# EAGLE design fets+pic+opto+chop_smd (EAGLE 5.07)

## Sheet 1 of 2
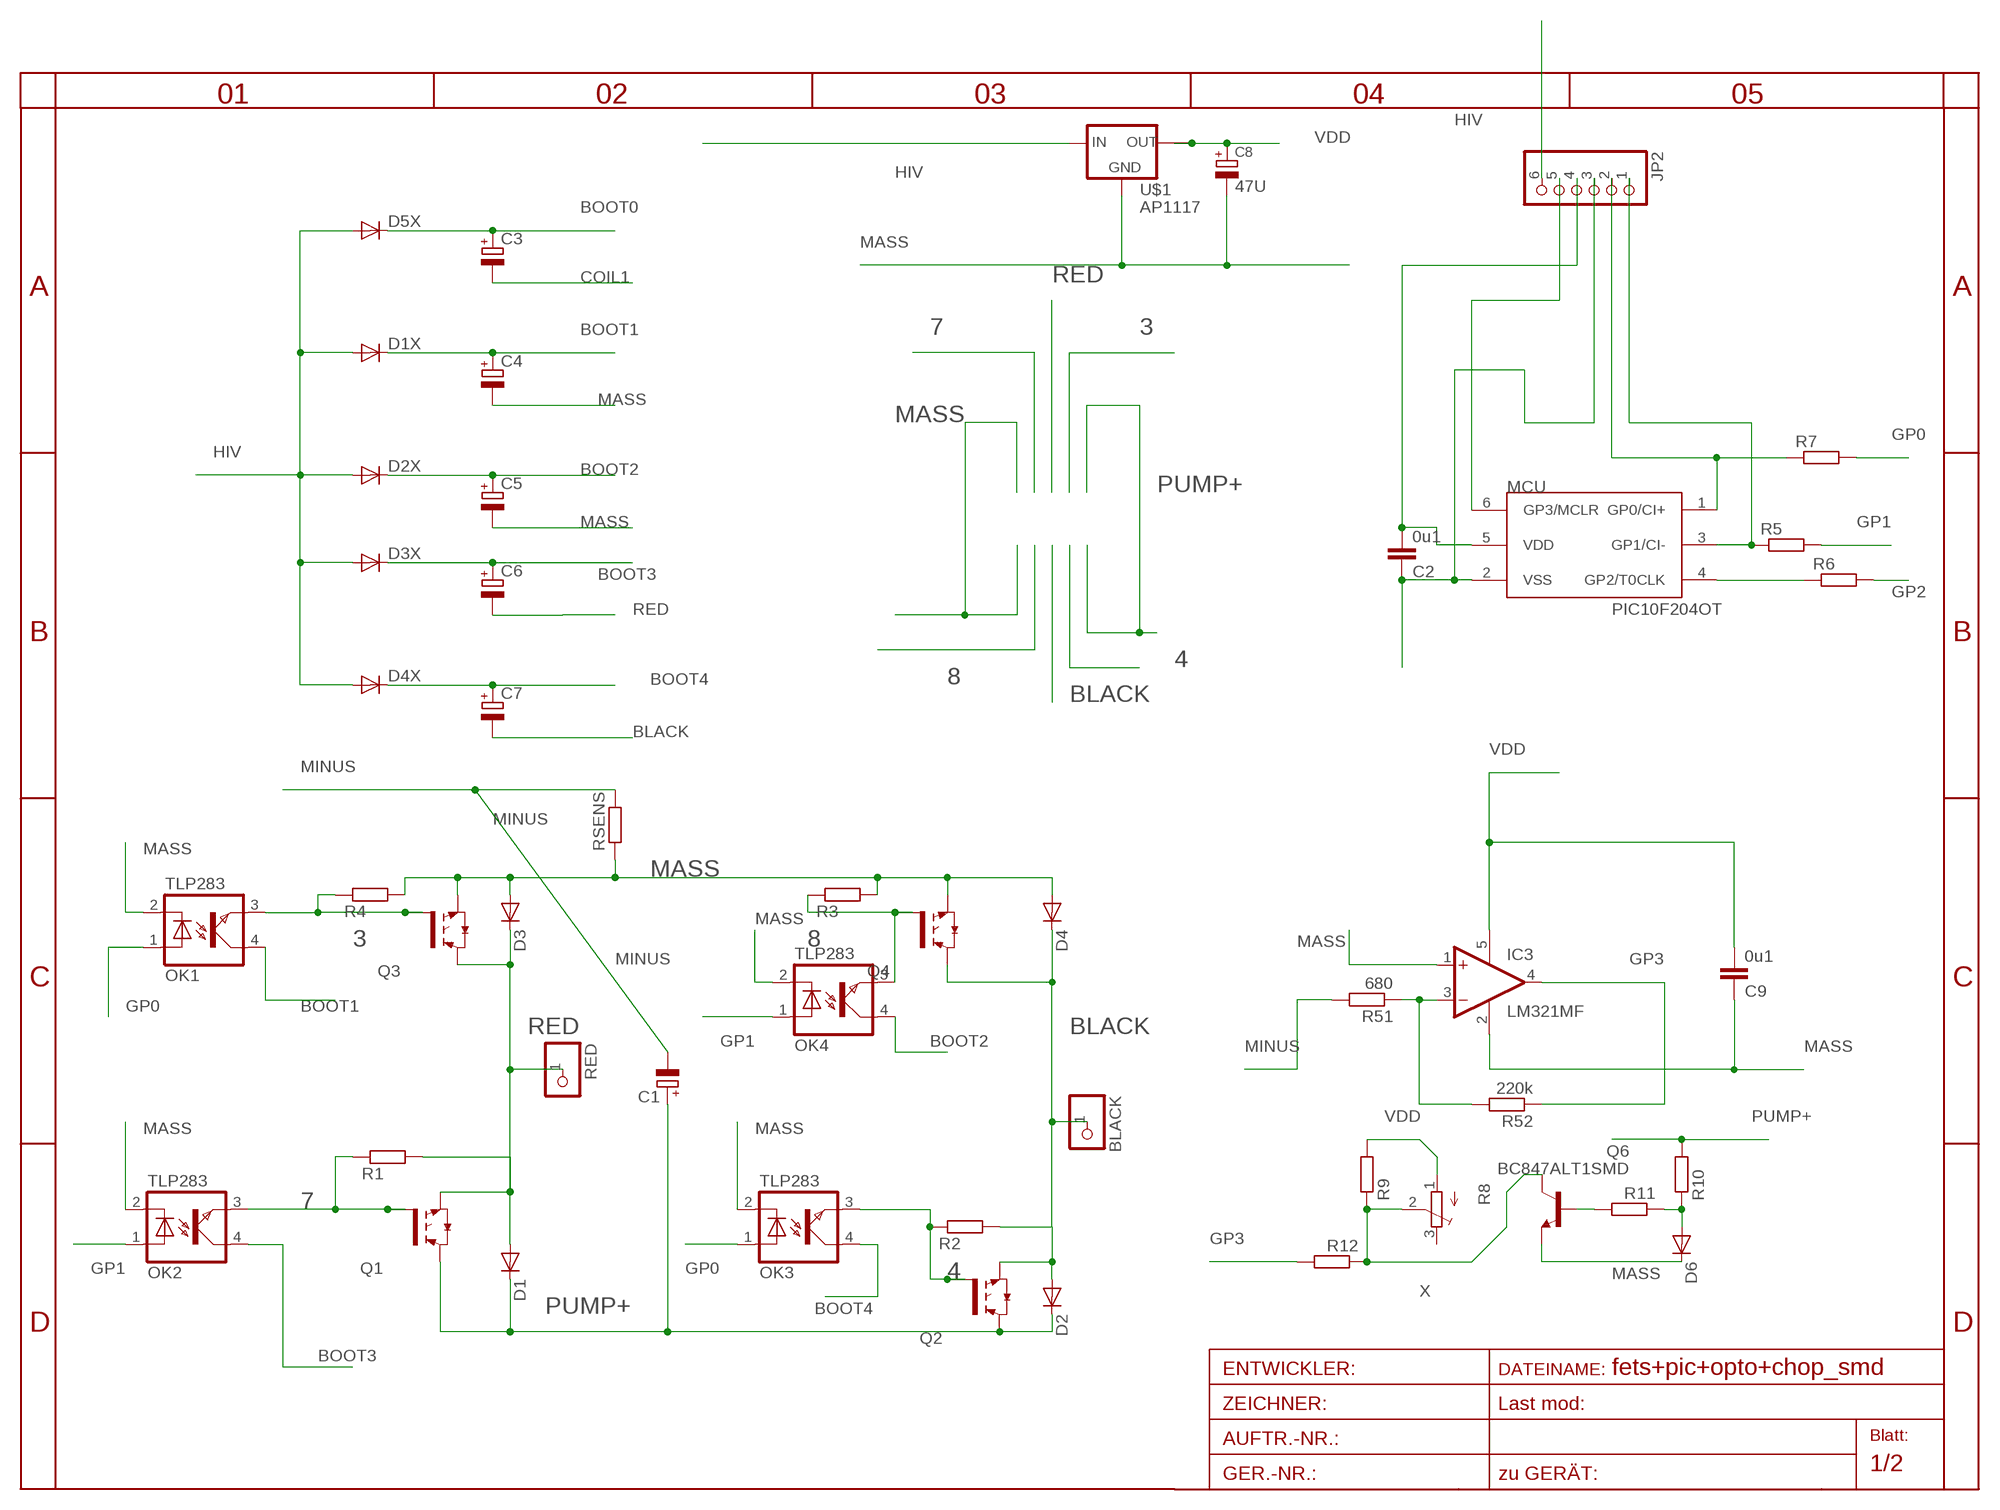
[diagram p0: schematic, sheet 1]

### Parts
BLACK  PINHD-1X14.5MM  [1X4MM5]
C1  CPOL-EUE5-13  [E5-13]
C2  0u1  C-EUC1206  [C1206]
C3  CPOL-EUC  [PANASONIC_C]
C4  CPOL-EUC  [PANASONIC_C]
C5  CPOL-EUC  [PANASONIC_C]
C6  CPOL-EUC  [PANASONIC_C]
C7  CPOL-EUC  [PANASONIC_C]
C8  47U  CPOL-EUC  [PANASONIC_C]
C9  0u1  C-EUC1206  [C1206]
D1  DIODE-SMC  [SMC]
D1X  DIODE-SMA-DO214  [SMA-DO214AC]
D2  DIODE-SMC  [SMC]
D2X  DIODE-SMA-DO214  [SMA-DO214AC]
D3  DIODE-SMC  [SMC]
D3X  DIODE-SMA-DO214  [SMA-DO214AC]
D4  DIODE-SMC  [SMC]
D4X  DIODE-SMA-DO214  [SMA-DO214AC]
D5X  DIODE-SMA-DO214  [SMA-DO214AC]
D6  DIODE-MINIMELF  [MINIMELF]
IC3  LM321MF  [SOT23-5]
JP2  PINHD-1X6  [1X06BOX]
MCU  PIC10F204OT  [SOT23-6]
OK1  TLP283  [MINI-FLAT-4]
OK2  TLP283  [MINI-FLAT-4]
OK3  TLP283  [MINI-FLAT-4]
OK4  TLP283  [MINI-FLAT-4]
Q1  IRG4BC15UD-S  [D2PACK]
Q2  IRG4BC15UD-S  [D2PACK]
Q3  IRG4BC15UD-S  [D2PACK]
Q4  IRG4BC15UD-S  [D2PACK]
Q6  BC847ALT1SMD  [SOT23]
R1  R-EU_R1206  [R1206]
R2  R-EU_R1206  [R1206]
R3  R-EU_R1206  [R1206]
R4  R-EU_R1206  [R1206]
R5  R-EU_R1206  [R1206]
R6  R-EU_R1206  [R1206]
R7  R-EU_R1206  [R1206]
R8  TRIM_EU-3223W  [3223W]
R9  R-EU_R1206  [R1206]
R10  R-EU_R1206  [R1206]
R11  R-EU_R1206  [R1206]
R12  R-EU_R1206  [R1206]
R51  680  R-EU_R0805  [R0805]
R52  220k  R-EU_R0805  [R0805]
RED  PINHD-1X14.5MM  [1X4MM5]
RSENS  R-EU_CERAM50  [CERAM50]
U$1  AP1117  [SOT223]

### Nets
3: OK1.3(EMIT) Q3.1(G) R4.1
4: OK3.3(EMIT) Q2.1(G) R2.1
7: OK2.3(EMIT) Q1.1(G) R1.1
8: OK4.3(EMIT) Q4.1(G) R3.1
BLACK: BLACK.1 C7.- D2.A D4.C Q2.3(E) Q4.2(C) R2.2
BOOT0: C3.+ D5X.K(C) ; also sheet 2
BOOT1: C4.+ D1X.K(C) OK1.4(COL)
BOOT2: C5.+ D2X.K(C) OK4.4(COL)
BOOT3: C6.+ D3X.K(C) OK2.4(COL)
BOOT4: C7.+ D4X.K(C) OK3.4(COL)
COIL1: C3.- ; also sheet 2
GP0: OK1.1(A) OK3.1(A) R7.2
GP0I: JP2.2 MCU.1(GP0/CI+) R7.1
GP1: OK2.1(A) OK4.1(A) R5.2
GP1I: JP2.1 MCU.3(GP1/CI-) R5.1
GP2: R6.2 ; also sheet 2
GP2I: MCU.4(GP2/T0CLK) R6.1
GP3: IC3.4(OUT) JP2.5 MCU.6(GP3/MCLR) R12.2 R52.1
HIV: D1X.A D2X.A D3X.A D4X.A D5X.A JP2.6 U$1.3(IN) ; also sheet 2
MASS: C2.1 C4.- C5.- C8.- C9.1 D3.A D4.A D6.C IC3.1(+IN) IC3.2(V-) JP2.3 MCU.2(VSS) OK1.2(C) OK2.2(C) OK3.2(C) OK4.2(C) Q3.3(E) Q4.3(E) Q6.2(E) R3.2 R4.2 RSENS.1 U$1.1(GND) ; also sheet 2
MINUS: C1.- R51.2 RSENS.2 ; also sheet 2
N$4: D6.A R10.1 R11.1
N$5: Q6.1(B) R11.2
N$52: IC3.3(-IN) R51.1 R52.2
PUMP+: C1.+ D1.C D2.C Q1.2(C) Q2.2(C) R10.2 ; also sheet 2
RED: C6.- D1.A D3.C Q1.3(E) Q3.2(C) R1.2 RED.1
VDD: C2.2 C8.+ C9.2 IC3.5(V+) JP2.4 MCU.5(VDD) R8.1(A) R9.2 U$1.2(OUT) U$1.4(TAB)
X: Q6.3(C) R8.2(S) R9.1 R12.1
Unconnected: R8.3(E)

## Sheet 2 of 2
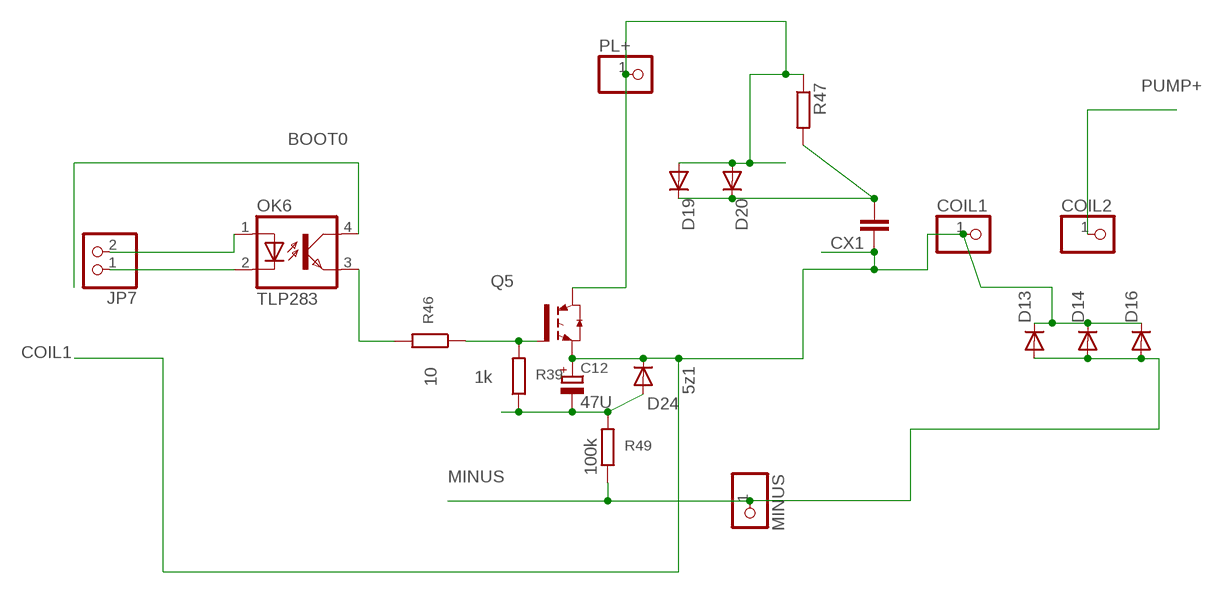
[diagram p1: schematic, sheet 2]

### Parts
C12  47U  CPOL-EUC  [PANASONIC_C]
COIL1  PINHD-1X14.5MM  [1X4MM5]
COIL2  PINHD-1X14.5MM  [1X4MM5]
CX1  CXXC15B6  [XC15B6]
D13  DIODE-SMC  [SMC]
D14  DIODE-SMC  [SMC]
D16  DIODE-SMC  [SMC]
D19  DIODE-SMC  [SMC]
D20  DIODE-SMC  [SMC]
D24  5z1  DIODE-MINIMELF  [MINIMELF]
JP7  PINHD-1X2STR  [1X02]
MINUS  PINHD-1X14.5MM  [1X4MM5]
OK6  TLP283  [MINI-FLAT-4]
PL+  PINHD-1X14.5MM  [1X4MM5]
Q5  IRG4BC15UD-S  [D2PACK]
R39  1k  R-EU_R1206  [R1206]
R46  10  R-EU_R1206  [R1206]
R47  R-EU_0613/15  [P0613/15]
R49  100k  R-EU_R0805  [R0805]

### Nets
BATT-: C12.- D24.A R39.1 R49.2
BOOT0: OK6.4(COL) ; also sheet 1
COIL1: C12.+ COIL1.1 CX1.1 D13.C D14.C D16.C D24.C Q5.3(E) ; also sheet 1
GP2: JP7.2 OK6.1(A) ; also sheet 1
HIV: D19.A D20.A PL+.1 Q5.2(C) R47.1 ; also sheet 1
MASS: JP7.1 OK6.2(C) ; also sheet 1
MINUS: D13.A D14.A D16.A MINUS.1 R49.1 ; also sheet 1
N$43: OK6.3(EMIT) R46.2
N$45: Q5.1(G) R39.2 R46.1
PUMP+: COIL2.1 ; also sheet 1
SNUB: CX1.2 D19.C D20.C R47.2

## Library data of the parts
BLACK COIL1 COIL2 MINUS PL+ RED = pinhead:PINHD-1X1: PIN HEADER
C1 C3-C7 = rcl:CPOL-EU: POLARIZED CAPACITOR, European symbol
C2 C9 = rcl:C-EU: CAPACITOR, European symbol
C8 C12 = rcl-2:CPOL-EU: POLARIZED CAPACITOR, European symbol
CX1 = rcl:CX: X CAPACITOR
D1 D1X D2 D2X D3 D3X D4 D4X D5X D6 D13 D14 D16 D19 D20 D24 = diode:DIODE-: DIODE
IC3 = linear:LM321?*: Low Power Single Op Amp Source: http://cache.national.com/ds/LM/LM321.pdf
JP2 = pinhead:PINHD-1X6: PIN HEADER
JP7 = pinhead:PINHD-1X2: PIN HEADER
MCU = microchip-3:PIC10F2*: uPC nW 0,25/0,5k Program Flash memory Comparator
OK1-OK4 OK6 = optocoupler:TLP283: TOSHIBA PHOTOCOUPLER GaAs IRED & PHOTO-TRANSISTOR Source: http://www.semicon.toshiba.co.jp/td/en/Opto/Photocoupler/en_20050928_TLP283_datasheet.pdf
Q1-Q5 = transistor-power:IRG4BC15UD-: INSULATED GATE BIPOLAR TRANSISTOR WITH ULTRAFAST SOFT RECOVERY DIODE
Q6 = transistor-npn:BC847*: NPN Transistor
R1-R7 R9-R12 R47 R51 R52 RSENS = rcl:R-EU_: RESISTOR, European symbol
R8 = pot:TRIM_EU-: POTENTIOMETER
R39 R46 R49 = rcl-2:R-EU_: RESISTOR, European symbol
U$1 = v-reg:AP1117

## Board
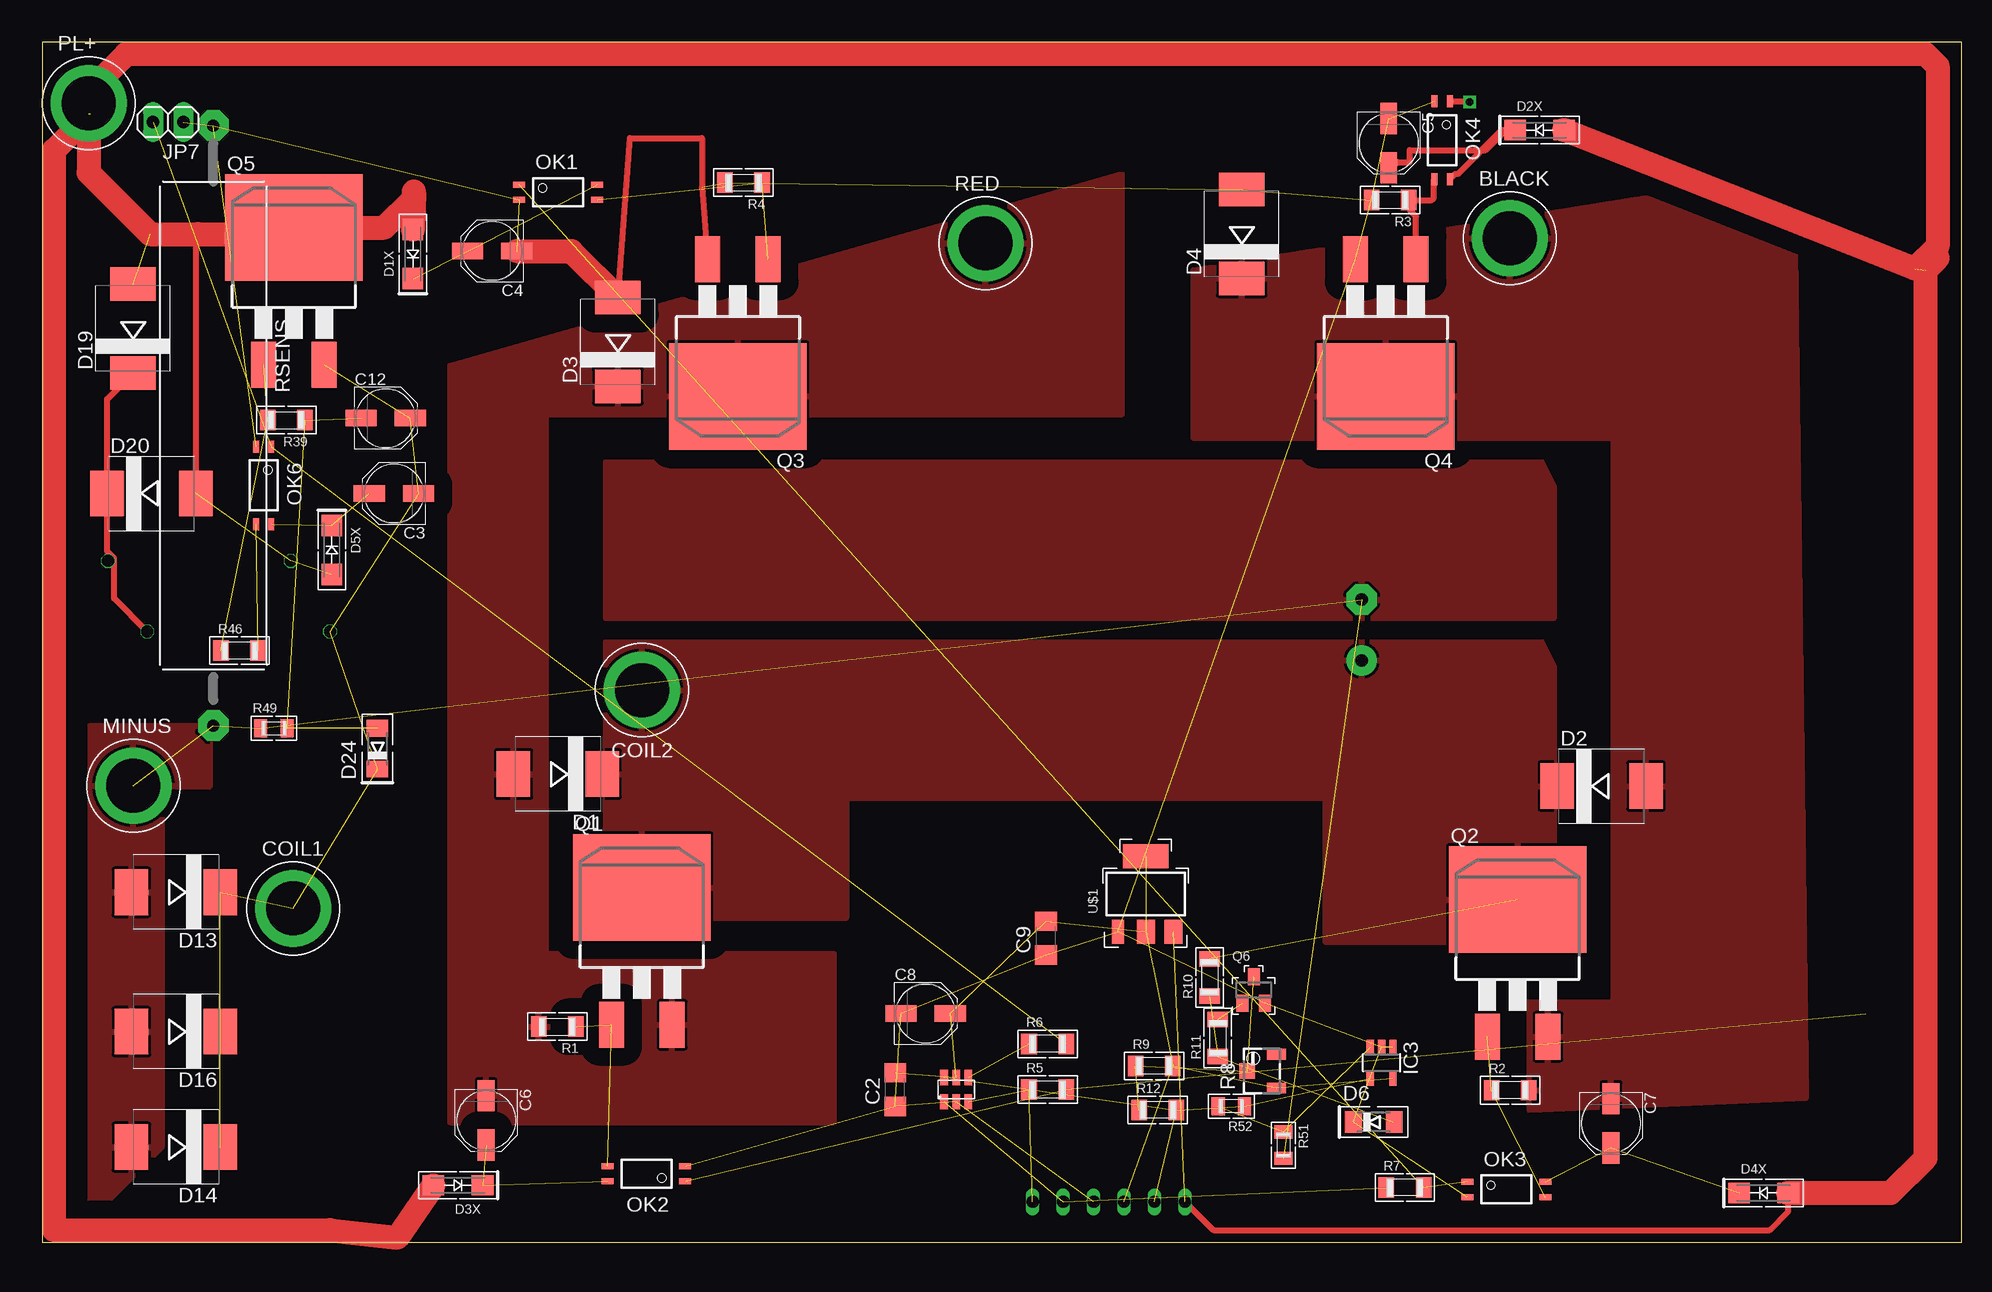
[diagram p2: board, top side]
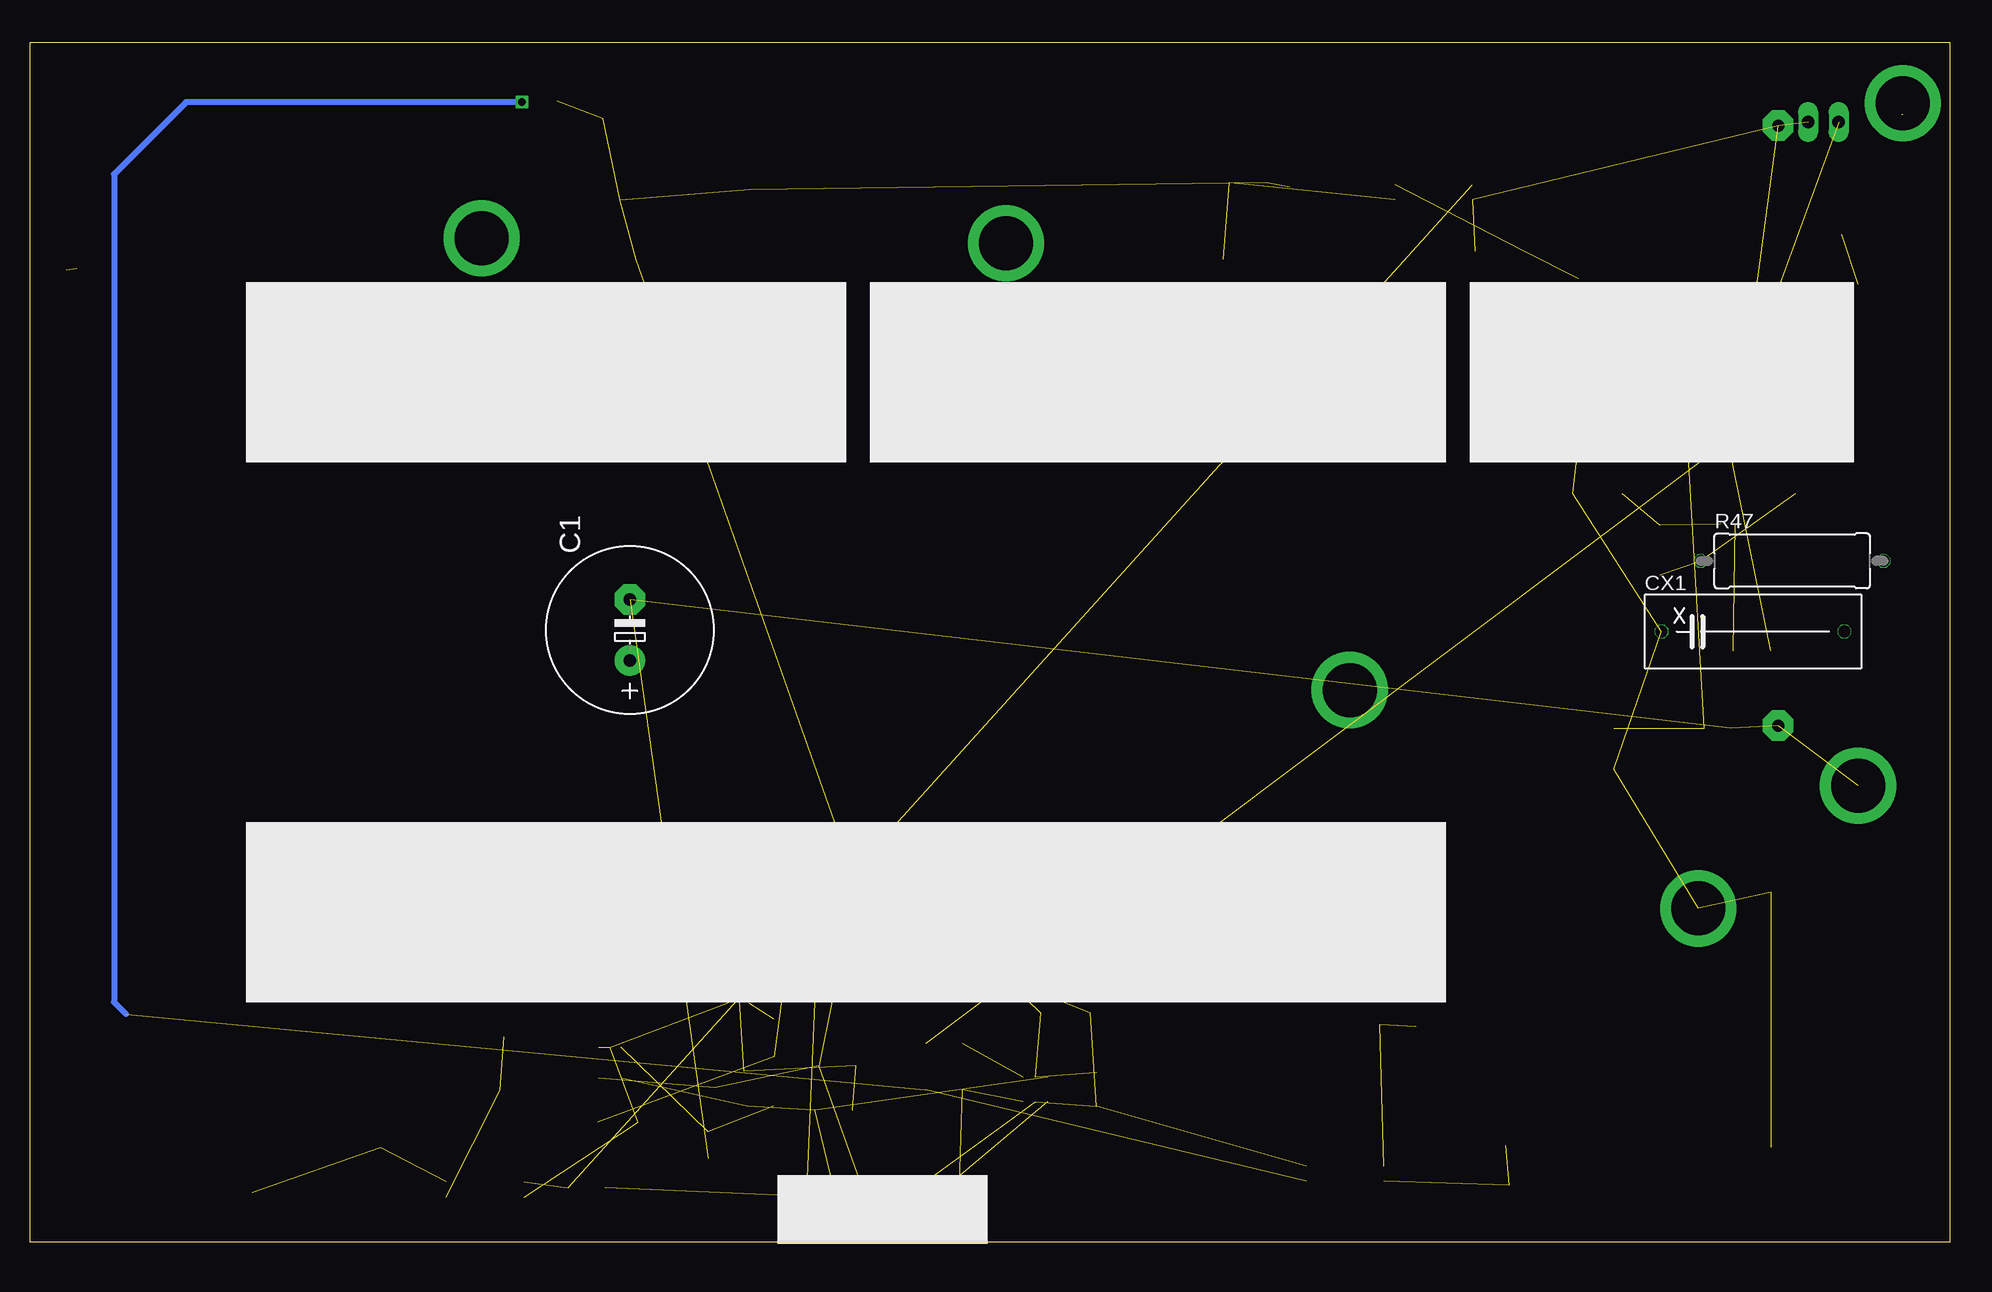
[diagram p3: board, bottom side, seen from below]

Size 160 x 100 mm. Coordinates in mm from the lower left corner, seen from the top.
Outline: 0,0 160,0 160,100 0,100 0,0
Copper layers (1*16): Top 0.035mm / dielectric 1.5mm / Bottom 0.035mm
Design rules "default": minimum track width 10mil, minimum drill 20mil, track to track 8mil, track to pad 8mil, pad to pad 8mil, via to via 8mil, smd to smd 8mil, copper to edge 40mil, drill to drill 8mil, minimum pad ring 1mil, minimum via ring 8mil, stop-mask expansion 4mil, vias tented up to drill 0mil, thermal gap 10mil

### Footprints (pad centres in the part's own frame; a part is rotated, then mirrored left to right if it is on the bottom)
1X4MM5 = drill 4.5 pad 6.35 round: 1 0,0
E5-13 = drill 1.016 pad 2.54 round: + -2.54,0 | drill 1.016 pad 2.54 octagon: - 2.54,0
C1206 = smd 1.6 x 1.8: 1 -1.4,0; 2 1.4,0
PANASONIC_C = smd 2.6 x 1.4: + 2.05,0; - -2.05,0
XC15B6 = drill 1.016 octagon: 1 -7.62,0; 2 7.62,0
SMC = smd 2.8 x 3.8: A 3.7,0; C -3.7,0
SMA-DO214AC = smd 1.8 x 1.7: A 2.05,-0.127; K -2.05,-0.127
MINIMELF = smd 1.4 x 1.8: A 1.7,0; C -1.7,0
SOT23-5 = smd 0.6 x 1.2: 1 -0.95,-1.306; 2 0,-1.306; 3 0.95,-1.306; 4 0.95,1.306; 5 -0.95,1.306
1X06BOX = drill 1.016 long: 1 -6.35,0; 2 -3.81,0; 3 -1.27,0; 4 1.27,0; 5 3.81,0; 6 6.35,0
1X02 = drill 1.016 pad 1.676 long: 1 -1.27,0; 2 1.27,0
SOT23-6 = smd 0.635 x 1.27: 1 -1.016,-1.016; 2 0,-1.016; 3 1.016,-1.016; 4 1.016,1.016; 5 0,1.016; 6 -1.016,1.016
MINI-FLAT-4 = smd 1 x 0.5: 1 -3.24,0.635; 2 -3.24,-0.635; 3 3.24,-0.635; 4 3.24,0.635
D2PACK = smd 2.083 x 3.81: 1 -2.54,-8.89; 3 2.54,-8.89 | smd 11.43 x 8.89: 2 0,2.54
SOT23 = smd 1 x 1.4: 1 -0.95,-1.1; 2 0.95,-1.1; 3 0,1.1
R1206 = smd 1.3 x 1.7: 1 -1.55,0; 2 1.55,0
3223W = smd 0.9 x 1.6: 1 -1.4,-1.215; 3 1.4,-1.215 | smd 1.3 x 1.3: 2 0,1.215
P0613/15 = drill 1.016 octagon: 1 -7.62,0; 2 7.62,0
R0805 = smd 1.1 x 1.5: 1 -1.1,0; 2 1.1,0
CERAM50 = drill 1 pad 2.54 octagon: 1 -25,0; 2 25,0
SOT223 = smd 1 x 2: 1 -2.3,-3.15 | smd 1.5 x 2: 2 0,-3.15; 3 2.3,-3.15 | smd 3.8 x 2: 4 0,3.15

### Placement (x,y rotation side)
BLACK  122.35,83.64 0 top
C1  110,51 90 bottom
C2  71.12,12.7 90 top
C3  29.34,62.37 180 top
C4  37.52,82.58 180 top
C5  112.25,91.57 270 top
C6  37.02,10.13 270 top
C7  130.78,9.89 270 top
C8  73.66,19.05 0 top
C9  83.69,25.32 90 top
C12  28.65,68.66 0 top
COIL1  20.94,27.8 0 top
COIL2  50,46 180 top
CX1  16.39,50.87 0 bottom
D1  43,39 180 top
D1X  30.79,82.34 90 top
D2  130,38 0 top
D2X  124.83,92.78 0 top
D3  48,75 90 top
D3X  34.68,4.6 180 top
D4  100,84 90 top
D4X  143.51,4.22 0 top
D5X  24.29,57.66 270 top
D6  111,10 0 top
D13  11.16,29.15 180 top
D14  11.16,7.91 180 top
D16  11.16,17.53 180 top
D19  7.59,76.12 90 top
D20  9.12,62.38 0 top
D24  27.96,41.11 90 top
IC3  111.66,14.94 180 top
JP2  88.93,3.35 180 bottom
JP7  10.52,93.33 180 top
MCU  76.2,12.7 0 top
MINUS  7.62,38.02 0 top
OK1  43.01,87.48 0 top
OK2  50.38,5.68 180 top
OK3  122.06,4.38 0 top
OK4  116.71,91.81 270 top
OK6  18.48,63.05 270 top
PL+  3.89,94.9 0 top
Q1  50,27 0 top
Q2  123,26 0 top
Q3  58,73 180 top
Q4  112,73 180 top
Q5  21,82 0 top
Q6  101,21 0 top
R1  42.95,17.95 180 top
R2  122.38,12.65 0 top
R3  112.38,86.83 180 top
R4  58.47,88.29 180 top
R5  83.82,12.7 0 top
R6  83.82,16.51 0 top
R7  113.6,4.54 0 top
R8  101.68,14.24 90 top
R9  92.7,14.67 0 top
R10  97.33,22.05 90 top
R11  98,17 90 top
R12  93,11 0 top
R39  20.37,68.49 180 top
R46  16.46,49.28 0 top
R47  13.12,56.76 0 bottom
R49  19.34,42.81 0 top
R51  103.48,8.07 270 top
R52  99.14,11.31 180 top
RED  78.65,83.23 0 top
RSENS  14.29,68.04 270 top
U$1  92,29 0 top

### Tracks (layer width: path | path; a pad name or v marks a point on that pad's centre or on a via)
3  (2 unrouted)
4  (2 unrouted)
7  (2 unrouted)
8
  Top 0.5: Q4.1 114.54,85.46 114,86 114,86.76 R3.1 115.83,86.83 116,87 116,88.5 OK4.3
BATT-  (3 unrouted)
BLACK
  pour Top (isolate 1.5, rank 2): 96,81 146,89 147,12 124,11 124,20 131,20 131,67 96,67
BOOT0  (2 unrouted)
BOOT1  (2 unrouted)
BOOT2
  Top 0.5: 122,92.65 121.65,92.65 118,89 117.78,89 OK4.4 | 122,92.65 D2X.K | C5.+ 112.52,89.52 113,90 114,90 114,91 120.35,91 122,92.65
BOOT3  (2 unrouted)
BOOT4  (2 unrouted)
COIL1  (8 unrouted)
GP0  (2 unrouted)
GP0I  (2 unrouted)
GP1  (via drill 0.6)  (2 unrouted)
  Top 0.5: OK4.1 118.95,95.05 v119,95
  Bottom 0.5: v119,95 147,95 153,89 153,20 152,19
GP1I  (2 unrouted)
GP2  (2 unrouted)
GP2I  (1 unrouted)
GP3  (4 unrouted)
HIV  (6 unrouted)
  Top 0.5: D4X.A 145.56,2.56 144,1 97.63,1 JP2.6 | D20.A 12.82,83.82 13,84
  Top 2: 3.89,94 3.89,89.11 9,84 13,84 20.46,84 Q5.2 28.54,84.54 31,87 31,87.53 D1X.A | 3.89,94 PL+.1 | D2X.A 156.12,81.12 158,83 158,98 157,99 7,99 3,95 3,94.89 3.89,94 | D4X.A 154.09,4.09 157,7 157,81 158,82 | D3X.A 29.63,0.37 24,1 1,1 1,91 4,94
MASS  (22 unrouted)
  Top 0.5: Q3.3 55,87.89 55,92 49,92 D3.A
  Top 2: C4.- 44.12,82.58 D3.A
MINUS  (4 unrouted)
  pour Top (isolate 1.5): 126,52 47,52 47,65 125,65 126,63
  pour Top (isolate 1.5, rank 3): 4,43 4,2 10,8 10,38 14,38 14,43
N$4  (2 unrouted)
N$5  (1 unrouted)
N$43  (1 unrouted)
N$45  (2 unrouted)
N$52  (2 unrouted)
PUMP+  (1 unrouted)
  pour Top (isolate 1.5): 126,48 126,25 107,25 107,37 67,37 67,27 47,27 47,50 125,50
RED
  pour Top (isolate 1.5, rank 2): 90,69 90,89 34,73 34,10 66,10 66,24 42,24 42,69
SNUB
  Top 0.5: D19.C 5.42,70.25 D20.C 5.42,57.58 6,57 | 6,57 6,53.64 CX1.2 | R47.2 5.76,56.76 6,57
VDD  (9 unrouted)
X  (3 unrouted)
